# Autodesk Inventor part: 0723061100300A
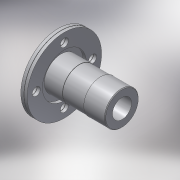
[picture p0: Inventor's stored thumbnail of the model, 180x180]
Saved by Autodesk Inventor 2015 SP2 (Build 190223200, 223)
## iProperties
Created: 2017-02
Part Number: 0723061100300A
Material: PVC-Piping
Description: PLASSON FLANGE ADAPTOR WITH METAL FLANGE 110-3"
Document SubType Name: Modeling
Designer: KIM
Mass: 92.6774 g
Surface Area: 199.44 cm^2
Volume: 66.1981 cm^3
Density: 1.4 g/cm^3
Appearance: Smooth - White
Author: Кирилл
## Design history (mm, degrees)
derived "872306.ipt"
feature "Solid1::872306.ipt"
tag "TaggingFeature1"
body "Solid1"
other parameters: "d73" = 21, "d74" = 90 deg, "d75" = 0.3, "d77" = 18, "d80" = 0, "d82" = 360 deg, "d96" = 0.3, "d99" = 360 deg, "d104" = 2.2, "d107" = 132, "d108" = 5.25, "d116" = 107.8, "d120" = 5.5, "S_" = 18
